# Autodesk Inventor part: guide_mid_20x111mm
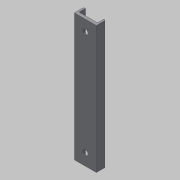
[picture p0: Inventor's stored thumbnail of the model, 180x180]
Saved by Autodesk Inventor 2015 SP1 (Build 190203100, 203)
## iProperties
Created: 2015-06
Part Number: guide_mid_20x111mm
Material: Generic
Document SubType Name: Modeling
Designer: uidn2323
Density: 1 g/cm^3
Appearance: Default
Author: uidn2323
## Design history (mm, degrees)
sketch "Sketch1"
  geometry: L1 (0, 0)-(19, 0); L2 (19, 0)-(19, 7); L3 (0, 7)-(0, 0); L4 (1.5, 2.5)-(17.5, 2.5); L5 (17.5, 2.5)-(17.5, 8); L6 (1.5, 8)-(1.5, 2.5); L7 (18, 8)-(17.5, 8); L8 (1.5, 8)-(1, 8); A1 r 1 centre (1, 7) between (1, 8) and (0, 7); A2 r 1 centre (18, 7) between (19, 7) and (18, 8); 3 further points
  constraints: 16 end point, 4 parallel, 4 point on circle, 4 point on line, 4 tangent, 2 centre point, 2 horizontal, 2 perpendicular, 1 equal radius
  dimensions: "d1" = 8 distance of point (19, 8) L1.end; "d4" = 1 radius of A1; "d5" = 2.5 distance between parallel lines of L1 L4; "d16" = 16 distance between parallel lines of L5 L6; "d18" = 1.5 distance between parallel lines of L3 L6; "d19" = 1.5 distance between parallel lines of L2 L5; "d30" = 8 distance between parallel lines of L1 L8
extrude "Extrusion1" new body sketch "Sketch1" distance "d6" = 110; taper "d7" = 0 deg
sketch "Sketch2"
  geometry: L1 (0, 0)-(0, -110) reference; L2 (16, -110)-(0, -110) reference; L3 (16, 0)-(0, 0) reference; C1 r 2.25 at (8, -100.5); C2 r 2.25 at (8, -10); 1 further point
  constraints: 2 centre point
  dimensions: "d8" = 4.5 diameter of C1; "d9" = 4.5 diameter of C2; "d20" = 8 distance from line of L1 C1.centre; "d22" = 8 distance from line of L1 C2.centre
extrude "Extrusion3" cut sketch "Sketch2" distance "d23" = 10; taper "d24" = 0 deg
chamfer "Chamfer2" distance "d25" = 2; stored, may be unused: second distance "d26" = 2, angle "d27" = 45 deg
body "Solid1"
